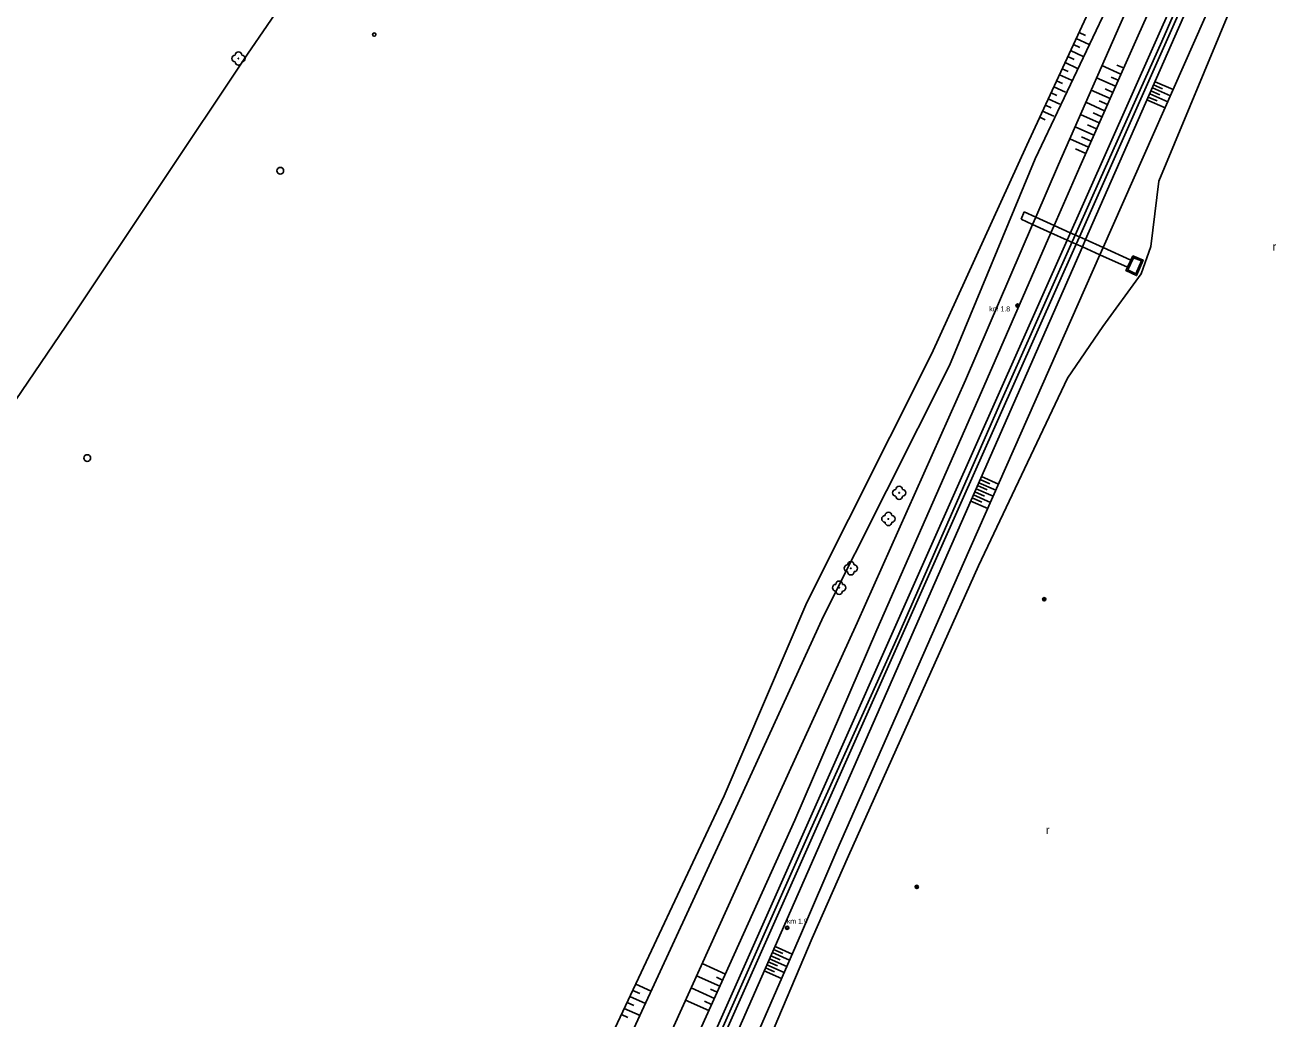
# Model space of a CAD drawing. Extents: x -539694 to -539148, y -1156467 to -1155920.
# Drawn here: x -539385.3 to -539197.8, y -1156272.3 to -1156123.3 of the extents above; entities that cross this region are included whole.
import ezdxf

# ---------------------------------------------------------------- set-up
doc = ezdxf.new("R2010")
doc.units = 0
for name, color, linetype in [('Vrstva 11', 7, 'Continuous'), ('Vrstva 12', 7, 'Continuous'), ('Vrstva 13', 7, 'Continuous'), ('Vrstva 14', 7, 'Continuous'), ('Vrstva 15', 7, 'Continuous'), ('Vrstva 22', 7, 'Continuous'), ('Vrstva 23', 7, 'Continuous'), ('Vrstva 25', 7, 'Continuous'), ('Vrstva 27', 7, 'Continuous'), ('Vrstva 28', 7, 'Continuous'), ('Vrstva 36', 7, 'Continuous'), ('Vrstva 41', 7, 'Continuous'), ('Vrstva 7', 7, 'Continuous')]:
    doc.layers.add(name, color=color, linetype=linetype)

msp = doc.modelspace()

# ---------------------------------------------------------------- linework, layer by layer
at = {"layer": 'Vrstva 11'}
msp.add_line((-539235.565, -1156151.324), (-539236.015, -1156152.436), dxfattribs=at)
for points in [[(-539235.565, -1156151.324), (-539233.801, -1156152.119), (-539231.058, -1156153.354), (-539228.629, -1156154.448), (-539227.275, -1156155.059)], [(-539236.015, -1156152.436), (-539234.275, -1156153.22), (-539231.538, -1156154.453), (-539229.117, -1156155.543), (-539227.762, -1156156.154)], [(-539227.275, -1156155.059), (-539226.336, -1156155.482), (-539223.699, -1156156.669), (-539219.544, -1156158.541)], [(-539227.762, -1156156.154), (-539226.818, -1156156.579), (-539224.184, -1156157.766), (-539220.065, -1156159.621)], [(-539219.25, -1156157.93), (-539219.544, -1156158.541), (-539220.065, -1156159.621), (-539220.3, -1156160.11), (-539218.69, -1156160.87), (-539217.72, -1156158.54), (-539219.25, -1156157.93)], [(-539218.794, -1156160.6), (-539217.983, -1156158.651), (-539219.151, -1156158.185), (-539220.032, -1156160.015), (-539218.794, -1156160.6)]]:
    msp.add_lwpolyline(points, dxfattribs=at)
at = {"layer": 'Vrstva 12'}
for p, q in [((-539209.89, -1156112.37), (-539249.61, -1156201.56)), ((-539227.275, -1156155.059), (-539208.62, -1156113.13)), ((-539227.762, -1156156.154), (-539227.275, -1156155.059)), ((-539248.28, -1156202.27), (-539227.762, -1156156.154)), ((-539249.61, -1156201.56), (-539268.71, -1156244.59)), ((-539267.32, -1156245.04), (-539248.28, -1156202.27)), ((-539268.71, -1156244.59), (-539289.44, -1156291.13)), ((-539288.07, -1156291.72), (-539267.32, -1156245.04))]:
    msp.add_line(p, q, dxfattribs=at)
for centre, radius in [((-539236.54, -1156165.37), 0.25), ((-539236.54, -1156165.37), 0.03), ((-539271.07, -1156258.58), 0.25), ((-539271.07, -1156258.58), 0.03)]:
    msp.add_circle(centre, radius, dxfattribs=at)
at = {"layer": 'Vrstva 13'}
for p, q in [((-539214.92, -1156125.78), (-539209.23, -1156112.62)), ((-539224.19, -1156146.54), (-539214.92, -1156125.78)), ((-539239.04, -1156179.79), (-539224.19, -1156146.54)), ((-539254.52, -1156215.03), (-539239.04, -1156179.79)), ((-539267.5, -1156243.82), (-539254.52, -1156215.03)), ((-539283.54, -1156279.77), (-539267.5, -1156243.82))]:
    msp.add_line(p, q, dxfattribs=at)
at = {"layer": 'Vrstva 14'}
for p, q in [((-539233.91, -1156143.39), (-539217.24, -1156108.26)), ((-539230.39, -1156144.21), (-539215.28, -1156109.8)), ((-539218.48, -1156124.89), (-539212.37, -1156111.34)), ((-539205.35, -1156115.23), (-539223.699, -1156156.669)), ((-539235.13, -1156141.3), (-539225.33, -1156120.1)), ((-539227.21, -1156144.55), (-539218.48, -1156124.89)), ((-539235.13, -1156141.3), (-539249.44, -1156172.64)), ((-539246.76, -1156174.36), (-539233.91, -1156143.39)), ((-539233.801, -1156152.119), (-539230.39, -1156144.21)), ((-539227.21, -1156144.55), (-539231.058, -1156153.354)), ((-539234.275, -1156153.22), (-539233.801, -1156152.119)), ((-539244.34, -1156176.56), (-539234.275, -1156153.22)), ((-539231.058, -1156153.354), (-539231.538, -1156154.453)), ((-539231.538, -1156154.453), (-539241.96, -1156178.3)), ((-539224.184, -1156157.766), (-539244.63, -1156203.94)), ((-539223.699, -1156156.669), (-539224.184, -1156157.766)), ((-539249.44, -1156172.64), (-539268.11, -1156209.85)), ((-539265.63, -1156211.91), (-539246.76, -1156174.36)), ((-539260.56, -1156212.89), (-539244.34, -1156176.56)), ((-539241.96, -1156178.3), (-539257.61, -1156213.93)), ((-539244.63, -1156203.94), (-539263.65, -1156247.01)), ((-539268.11, -1156209.85), (-539280.5, -1156238.83)), ((-539278.45, -1156239.99), (-539265.63, -1156211.91)), ((-539273.36, -1156240.91), (-539260.56, -1156212.89)), ((-539257.61, -1156213.93), (-539269.91, -1156242.48)), ((-539280.5, -1156238.83), (-539297.65, -1156275.3)), ((-539295.28, -1156276.38), (-539278.45, -1156239.99)), ((-539289.82, -1156277.16), (-539273.36, -1156240.91)), ((-539269.91, -1156242.48), (-539286.5, -1156279.16)), ((-539263.65, -1156247.01), (-539268.91, -1156259.37)), ((-539268.91, -1156259.37), (-539283.78, -1156293.21))]:
    msp.add_line(p, q, dxfattribs=at)
msp.add_lwpolyline([(-539301.35, -1156326.15), (-539226.818, -1156156.579), (-539226.336, -1156155.482), (-539207.8, -1156113.31)], dxfattribs=at)
at = {"layer": 'Vrstva 15'}
for p, q in [((-539227.747, -1156125.329), (-539225.805, -1156126.226)), ((-539227.327, -1156124.421), (-539226.345, -1156124.875)), ((-539228.586, -1156127.145), (-539226.689, -1156128.021)), ((-539228.166, -1156126.237), (-539227.207, -1156126.68)), ((-539229.425, -1156128.96), (-539227.573, -1156129.816)), ((-539229.005, -1156128.052), (-539228.068, -1156128.485)), ((-539221.046, -1156130.674), (-539223.891, -1156129.41)), ((-539220.64, -1156129.76), (-539221.635, -1156129.318)), ((-539230.683, -1156131.683), (-539229.791, -1156132.096)), ((-539230.264, -1156130.776), (-539228.457, -1156131.61)), ((-539229.844, -1156129.868), (-539228.93, -1156130.291)), ((-539221.858, -1156132.502), (-539224.695, -1156131.242)), ((-539221.452, -1156131.588), (-539222.524, -1156131.112)), ((-539231.522, -1156133.499), (-539230.653, -1156133.901)), ((-539231.103, -1156132.591), (-539229.341, -1156133.405)), ((-539222.67, -1156134.329), (-539225.5, -1156133.073)), ((-539222.264, -1156133.416), (-539223.412, -1156132.906)), ((-539216.544, -1156133.204), (-539215.22, -1156133.786)), ((-539216.334, -1156132.725), (-539213.624, -1156133.916)), ((-539216.142, -1156132.289), (-539214.817, -1156132.871)), ((-539215.931, -1156131.81), (-539213.219, -1156133.002)), ((-539232.361, -1156135.314), (-539231.514, -1156135.706)), ((-539231.942, -1156134.407), (-539230.225, -1156135.2)), ((-539223.482, -1156136.157), (-539226.303, -1156134.903)), ((-539223.076, -1156135.243), (-539224.3, -1156134.699)), ((-539217.138, -1156134.556), (-539214.434, -1156135.745)), ((-539216.947, -1156134.12), (-539215.622, -1156134.702)), ((-539216.736, -1156133.641), (-539214.029, -1156134.83)), ((-539233.2, -1156137.13), (-539232.376, -1156137.511)), ((-539232.781, -1156136.222), (-539231.109, -1156136.995)), ((-539224.294, -1156137.985), (-539227.108, -1156136.735)), ((-539223.888, -1156137.071), (-539225.189, -1156136.493)), ((-539225.105, -1156139.813), (-539227.912, -1156138.566)), ((-539224.699, -1156138.899), (-539226.077, -1156138.287)), ((-539225.917, -1156141.641), (-539228.716, -1156140.398)), ((-539225.511, -1156140.727), (-539226.965, -1156140.081)), ((-539226.323, -1156142.555), (-539227.854, -1156141.875)), ((-539242.135, -1156191.428), (-539240.669, -1156192.072)), ((-539241.94, -1156190.983), (-539239.389, -1156192.104)), ((-539242.94, -1156193.259), (-539241.474, -1156193.903)), ((-539242.744, -1156192.813), (-539240.199, -1156193.932)), ((-539242.538, -1156192.343), (-539241.072, -1156192.988)), ((-539242.342, -1156191.898), (-539239.794, -1156193.018)), ((-539243.549, -1156194.644), (-539241.008, -1156195.761)), ((-539243.343, -1156194.174), (-539241.876, -1156194.819)), ((-539243.147, -1156193.729), (-539240.604, -1156194.847)), ((-539273.496, -1156262.779), (-539272.14, -1156263.375)), ((-539273.292, -1156262.314), (-539270.704, -1156263.452)), ((-539273.094, -1156261.863), (-539271.738, -1156262.459)), ((-539272.89, -1156261.399), (-539270.301, -1156262.537)), ((-539280.33, -1156265.517), (-539283.828, -1156263.963)), ((-539274.301, -1156264.61), (-539272.945, -1156265.205)), ((-539274.097, -1156264.145), (-539271.508, -1156265.283)), ((-539273.899, -1156263.694), (-539272.543, -1156264.29)), ((-539273.695, -1156263.23), (-539271.106, -1156264.368)), ((-539281.154, -1156267.34), (-539284.655, -1156265.784)), ((-539280.742, -1156266.429), (-539281.686, -1156266.009)), ((-539274.499, -1156265.061), (-539271.911, -1156266.199)), ((-539294.202, -1156267.968), (-539293.169, -1156268.427)), ((-539293.776, -1156267.063), (-539291.449, -1156268.097)), ((-539281.978, -1156269.162), (-539285.482, -1156267.606)), ((-539281.566, -1156268.251), (-539282.574, -1156267.803)), ((-539295.054, -1156269.779), (-539294.057, -1156270.221)), ((-539294.628, -1156268.873), (-539292.289, -1156269.912)), ((-539282.802, -1156270.985), (-539286.309, -1156269.427)), ((-539282.39, -1156270.073), (-539283.462, -1156269.597)), ((-539295.905, -1156271.589), (-539294.945, -1156272.015)), ((-539295.479, -1156270.683), (-539293.128, -1156271.728))]:
    msp.add_line(p, q, dxfattribs=at)
at = {"layer": 'Vrstva 22'}
for centre in [(-539353.32, -1156128.34), (-539254.29, -1156193.42), (-539255.9, -1156197.33), (-539261.53, -1156204.73), (-539263.28, -1156207.63)]:
    msp.add_circle(centre, 0.05, dxfattribs=at)
for centre, start, end in [((-539353.82, -1156128.34), 90, 270), ((-539353.32, -1156127.84), 0, 180), ((-539352.82, -1156128.34), 270, 90), ((-539353.32, -1156128.84), 180, 0), ((-539254.79, -1156193.42), 90, 270), ((-539254.29, -1156192.92), 0, 180), ((-539253.79, -1156193.42), 270, 90), ((-539254.29, -1156193.92), 180, 0), ((-539256.4, -1156197.33), 90, 270), ((-539255.9, -1156196.83), 0, 180), ((-539255.4, -1156197.33), 270, 90), ((-539255.9, -1156197.83), 180, 0), ((-539262.03, -1156204.73), 90, 270), ((-539261.53, -1156204.23), 0, 180), ((-539261.03, -1156204.73), 270, 90), ((-539263.28, -1156207.13), 0, 180), ((-539261.53, -1156205.23), 180, 0), ((-539263.78, -1156207.63), 90, 270), ((-539263.28, -1156208.13), 180, 0), ((-539262.78, -1156207.63), 270, 90)]:
    msp.add_arc(centre, 0.5, start, end, dxfattribs=at)
at = {"layer": 'Vrstva 23'}
for p, q in [((-539202.8, -1156116.53), (-539215.34, -1156146.71)), ((-539215.34, -1156146.71), (-539216.57, -1156156.52)), ((-539216.57, -1156156.52), (-539218.03, -1156160.62)), ((-539218.03, -1156160.62), (-539223.75, -1156168.52)), ((-539223.75, -1156168.52), (-539229.03, -1156176.22)), ((-539229.03, -1156176.22), (-539242.39, -1156204.34)), ((-539242.39, -1156204.34), (-539261.89, -1156247.8)), ((-539261.89, -1156247.8), (-539267.32, -1156260.16)), ((-539267.32, -1156260.16), (-539281.71, -1156294.05))]:
    msp.add_line(p, q, dxfattribs=at)
at = {"layer": 'Vrstva 25'}
for centre, radius in [((-539232.54, -1156209.37), 0.25), ((-539232.54, -1156209.37), 0.2), ((-539232.54, -1156209.37), 0.15), ((-539232.54, -1156209.37), 0.1), ((-539232.54, -1156209.37), 0.05), ((-539251.65, -1156252.46), 0.25), ((-539251.65, -1156252.46), 0.2), ((-539251.65, -1156252.46), 0.15), ((-539251.65, -1156252.46), 0.1), ((-539251.65, -1156252.46), 0.05)]:
    msp.add_circle(centre, radius, dxfattribs=at)
at = {"layer": 'Vrstva 27'}
for centre in [(-539347.04, -1156145.15), (-539375.97, -1156188.2)]:
    msp.add_circle(centre, 0.5, dxfattribs=at)
at = {"layer": 'Vrstva 28'}
msp.add_circle((-539332.95, -1156124.76), 0.25, dxfattribs=at)
at = {"layer": 'Vrstva 7'}
for p, q in [((-539340.18, -1156110.47), (-539351.98, -1156127.71)), ((-539351.98, -1156127.71), (-539378.22, -1156167.03)), ((-539378.22, -1156167.03), (-539396.93, -1156194.53))]:
    msp.add_line(p, q, dxfattribs=at)

# ---------------------------------------------------------------- texts
at = {"layer": 'Vrstva 36'}
for p in [(-539198.312, -1156157.114), (-539232.295, -1156244.528)]:
    msp.add_text('r', height=1.2, dxfattribs=at).set_placement(p)
at = {"layer": 'Vrstva 41'}
for s, p in [('km 1.8', (-539240.765, -1156166.23)), ('km 1.9', (-539271.111, -1156257.977))]:
    msp.add_text(s, height=0.75, dxfattribs=at).set_placement(p)

doc.saveas('drawing.dxf')
